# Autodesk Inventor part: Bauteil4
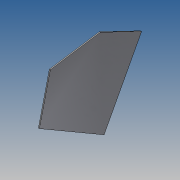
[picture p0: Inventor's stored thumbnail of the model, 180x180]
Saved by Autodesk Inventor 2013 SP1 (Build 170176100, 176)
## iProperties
Company: Kirow Ardelt GmbH
Created: 2013-01
Part Number: Bauteil4
Material: Stahl
Document SubType Name: Blech
Designer: Winkelmann
Density: 7.85 g/cm^3
Sheet Metal Rule: Standard (Ardelt)
Mass: 23816.8 g
Surface Area: 7777.97 cm^2
Volume: 3033.99 cm^3
Stärke: 8,000 mm
Biegeradius: 8,000 mm
BreiteBiegungsfreistellung: 8,000 mm
TiefeBiegungsfreistellung: 4,000 mm
GrößeEckenfreistellung: 32,000 mm
MinimalRest: 16,000 mm
Übergangsradius: 8,000 mm
JacobiRadiusGröße: 8,000 mm
Abstandsgröße: 8,000 mm
d0: 8,000 mm
Author: Winkelmann
Revision Number: A
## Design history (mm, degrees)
node "Fläche1"
  sketch "Skizze1"
    geometry: L1 (-318.13, 206.345)-(86.584, 266.588); L2 (86.584, 266.588)-(420.194, 105.525); L3 (420.194, 105.525)-(116.643, -467.157); L4 (116.643, -467.157)-(-406.665, -162.026); L5 (-406.665, -162.026)-(-318.13, 206.345); 1 further point
    constraints: 10 end point
node "Volumenkörper1"
feature "Grobblech1" dims "Stärke" = 8 (derived)
other parameters: "KFaktor" = 4.4, "Biegeradius" = 8 (= Stärke), "BreiteBiegungsfreistellung" = 8 (= Stärke), "TiefeBiegungsfreistellung" = 4 (= 0.5 x Stärke), "GrößeEckenfreistellung" = 32 (= 4 x Stärke), "AbstandVerbindung" = 0.01, "MinimalRest" = 16 (= 2 x Stärke), "Übergangsradius" = 8 (= Biegeradius), "JacobiRadiusGröße" = 8 (= Biegeradius), "Abstandsgröße" = 8 (= Stärke), "d0" = 8 (= Biegeradius)
